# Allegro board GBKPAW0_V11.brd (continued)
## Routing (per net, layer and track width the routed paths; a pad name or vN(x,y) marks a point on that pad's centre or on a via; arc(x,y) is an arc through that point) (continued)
P3V3_IN: length 20.7
  TOP w0.381: R109.2 v1(18.16,5.9)
  TOP w0.508: v1(19.05,5.9) 19.05,8.56 20.57,10.09 23.37,10.09 24,10.72 26.04,10.72 26.67,11.36 L1.2 26.67,14.53
  BOTTOM w0.254: 26.04,17.71 26.04,20.5 R168.2
  BOTTOM w0.381: v1(18.16,5.9) 18.1,5.96 FB129.2 18.03,6.72 R216.2
  vias: v1(28.32,15.3) v1(28.32,14.03) v1(28.32,12.76) v1(28.32,11.49)
P3V3_PG: length 1.4
  TOP w0.254: U7.9 v1(14.5,10.74)
  BOTTOM w0.381: v1(14.5,10.74) 14.51,10.72 R212.1
P3V3EN: length 5.7
  TOP w0.254: C35.2 13.59,9.07 14.2,9.69 U7.11
  TOP w0.381: R110.1 R105.1 C35.2
P5V: length 8.4
  TOP w0.381: R110.2 v1(11.56,5.9) ; R80.1 58.67,15.04 59.05,14.66 v1(59.05,11.36) ; R106.2 v1(13.84,5.9)
  BOTTOM w0.381: v1(51.56,11.99) 51.56,12.67 FB9.1
  vias: v1(13.84,32.69) v1(13.84,31.68) v1(14.73,14.28) v1(14.73,13.39) v1(14.99,32.69) v1(14.99,31.68) v1(15.62,14.28) v1(15.62,13.39) v1(21.08,22.41) v1(21.08,21.52) v1(21.84,23.42) v1(21.84,22.41) v1(21.84,21.14) v1(21.84,19.99) v1(80.52,16.82) v1(81.41,16.82) v1(82.3,14.28) v1(83.06,14.28)
P5V_ADC: length 2.9
  TOP w0.254: U5.2 54.56,15.48 v1(54.74,15.3)
  BOTTOM w0.381: v1(54.74,15.3) 54.61,15.17 C74.2 54.61,14.11 FB9.2
P5VSB: length 7.2
  TOP w0.254: R78.2 17.53,15.93 17.27,16.18 17.27,19.36
  BOTTOM w0.381: R149.1 R151.2 17.78,24.95
  vias: v1(17.53,23.8) v1(17.53,23.04) v1(17.53,22.28)
VBAT: length 22.2
  TOP w0.381: v1(22.35,36.09) 20.61,36.09 R51.2 ; v1(25.65,36.12) 25.65,26.34 C15.2 26.92,25.46 27.3,25.07 27.3,24.57 29.28,22.59 U2.74
  BOTTOM w0.381: v1(25.65,36.12) 25.62,36.09 v1(22.35,36.09)
ADC_IN0: length 2.9
  TOP w0.254: U5.15 52.7,13.77 52.95,13.53 53.2,13.53 ; R103.2 53.72,13.01 53.2,13.53 ; 53.2,13.53 U5.16
ADC_IN1: length 3.2
  TOP w0.254: U5.5 53.7,17.22 53.95,16.97 U5.4 55.54,16.48 R77.2
ADC_IN2: length 3.6
  TOP w0.254: 48.77,16.69 48.98,16.48 U5.9 50.95,16.91 51.27,17.22 U5.8
ADC_IN3: length 2.8
  TOP w0.254: 51.7,13.66 U5.13 ; 51.7,13.66 51.84,13.52 52.07,13.52 52.2,13.65 U5.14 ; 51.7,13.66 51.7,12.77 R102.2
ADCIN0: length 16.4
  TOP w0.254: R100.1 v1(46.55,13.64) ; R100.1 R99.1 ; R100.1 45.85,15.02 R86.2 ; C31.2 R104.1 56.77,12.37 56.39,11.99 v1(54.74,11.99)
  BOTTOM w0.254: v1(46.55,13.64) 46.99,13.64 49.66,10.98 53.72,10.98 v1(54.74,11.99)
ADCIN0+: length 3.5
  TOP w0.254: U5.1 53.95,13.67 54.99,12.63 R104.2
ADCIN1: length 22.5
  TOP w0.254: v1(53.72,11.99) 54.23,11.49 56.63,11.49 57.51,12.36 57.51,13.91 56.88,14.53 C28.2 R88.1 ; v1(45.34,14.28) 44.58,15.04 R85.2 43.43,15.02 R98.1 R97.1
  BOTTOM w0.254: v1(45.34,14.28) 47.24,14.28 50.04,11.49 53.21,11.49 v1(53.72,11.99)
ADCIN1+: length 2
  TOP w0.254: R88.2 55.33,15.98 U5.3
ADCIN2: length 12.4
  TOP w0.254: R96.1 41,13.67 R84.2 41.53,15.04 41.78,15.3 41.78,17.05 42.06,17.33 46.48,17.33 47.12,16.69 47.62,16.69 R87.1 C27.2
ADCIN2+: length 2.5
  TOP w0.254: R87.2 49.07,15.98 U5.10
ADCIN3: length 21.8
  TOP w0.254: v1(49.28,8.31) 42.42,8.31 41.69,9.04 41.69,10.69 R95.1 39.37,12.63 39.12,12.88 39.12,13.46 38.94,13.64 R94.1 38.48,14.94 R83.2 ; v1(47.62,11.99) R101.1 C30.2
  BOTTOM w0.254: v1(49.28,8.31) 49.28,10.34 v1(47.62,11.99)
AI0: length 4.4
  TOP w0.254: R100.2 v1(46.55,12.63)
  BOTTOM w0.254: 48.04,9.58 48.04,10.56 46.55,12.06 v1(46.55,12.63)
AI1: length 4.3
  TOP w0.254: R98.2 v1(44.07,12.63)
  BOTTOM w0.254: v1(44.07,12.63) 45.5,11.19 45.5,9.58
AI2: length 3.9
  TOP w0.254: 42.96,9.58 42.96,10.69 R96.2
AI3: length 3.9
  TOP w0.254: 40.42,9.58 40.42,10.69 R94.2
AI4: length 6.5
  BOTTOM w0.254: 48.04,7.04 46.77,8.31 46.77,10.94 45.85,11.87 R183.2
AI5: length 6.3
  BOTTOM w0.254: R186.2 39.15,12.08 39.15,8.31 40.42,7.04
AI6: length 6.4
  BOTTOM w0.254: R185.2 41.69,11.96 41.69,8.31 42.96,7.04
AI7: length 6.4
  BOTTOM w0.254: R184.2 43.43,11.99 44.23,11.19 44.23,8.31 45.5,7.04
CAN0_RX: length 2.1
  BOTTOM w0.152: R113.1 76.33,64.13 J4.4
CAN0_TX: length 2.4
  BOTTOM w0.152: R112.1 77.47,63.28 J4.3
CAN1_RX: length 2.4
  BOTTOM w0.152: R115.1 74.04,63.47 J4.6
CAN1_TX: length 2
  BOTTOM w0.152: R114.1 75.18,64.32 J4.5
CAN2_RX: length 2.1
  BOTTOM w0.152: R117.1 60.71,64.13 J3.4
CAN2_TX: length 2.4
  BOTTOM w0.152: R116.1 61.85,63.27 J3.3
CAN3_RX: length 2.4
  BOTTOM w0.152: R119.1 58.42,63.47 J3.6
CAN3_TX: length 2
  BOTTOM w0.152: R118.1 59.56,64.32 J3.5
CARD_DET: length 6.2
  BOTTOM w0.152: SDCARD1.9 15.06,45.57 15.49,45.14 17.53,45.14 D36.2 R142.2
CH340_P5V: length 6
  TOP w0.381: v1(23.11,31.55) C13.1 22.95,32.35 U3.1
  BOTTOM w0.381: 22.48,28.88 22.48,30.92 v1(23.11,31.55)
  vias: v1(22.1,27.87) v1(22.1,26.6) v1(23.24,26.6)
CH_RXD: length 7.2
  TOP w0.152: U4.9 21.45,29.38 21.72,29.65 21.72,30.31 22.47,31.07 24.33,31.07 24.77,31.5 24.77,32.57 R56.1
CH_TXD: length 9.6
  TOP w0.152: R54.1 25.15,33.33 25.15,31.35 24.49,30.69 22.63,30.69 22.1,30.15 22.1,29.14 21.34,28.38 U4.8
CHRXD: length 111.4
  TOP w0.152: U3.7 v1(16.38,33)
  BOTTOM w0.152: 62.61,58.48 58.25,58.48 54.88,61.84 54.88,65.15 53.1,66.93 24.58,66.93 20.71,63.06 10.94,63.06 8.76,60.89 8.13,60.89 6.1,58.86 2.41,58.86 0.58,57.03 0.58,37.41 5.05,32.95 7.24,32.95 7.87,33.58 15.8,33.58 v1(16.38,33)
CHTXD: length 110.1
  TOP w0.152: U3.6 16.69,33.65 v1(16.38,33.96)
  BOTTOM w0.152: 62.61,57.33 58.83,57.33 54.48,61.68 54.48,64.98 52.94,66.53 24.74,66.53 20.88,62.67 11.18,62.67 8.89,60.38 8.25,60.38 6.22,58.35 2.62,58.35 1.02,56.74 1.02,37.65 5.38,33.28 6.93,33.28 7.62,33.96 v1(16.38,33.96)
CPU_ADC_IN0: length 24
  TOP w0.254: U2.102 56.49,18.75 57.89,17.35 57.89,15.01 58.44,14.45 v1(58.44,14.04) ; R103.1 v1(52.7,11.99) 52.07,11.36 45.97,11.36 R99.2
  BOTTOM w0.254: v1(52.7,11.99) 53.34,12.63 57.02,12.63 58.44,14.04 v1(58.44,14.04)
CPU_ADC_IN1: length 29.8
  TOP w0.254: U2.100 54.69,20.4 v1(53.21,18.93) ; R97.2 44.07,10.85 56.64,10.85 57.96,12.17 57.96,14.23 57.4,14.79 57.4,16.06 R77.1 56.77,17.55 v1(55.4,18.92)
  BOTTOM w0.254: v1(53.21,18.93) 55.39,18.93 v1(55.4,18.92)
CPU_ADC_IN2: length 6.9
  TOP w0.254: R75.2 R76.1 49.79,17.71 52.89,20.81 U2.98
CPU_ADC_IN3: length 28.6
  TOP w0.254: R102.1 v1(50.55,11.99) ; R95.2 39.75,16.95 41.15,18.34 v1(44.7,18.34) 45.34,18.98 49.4,18.98 51.09,20.66 U2.96
  BOTTOM w0.254: v1(50.55,11.99) 50.55,16.82 49.81,17.56 45.49,17.56 v1(44.7,18.34)
CPU_ADC_IN4: length 16.3
  TOP w0.254: U2.101 55.59,20.34 53.47,18.22 51.66,18.22 50.52,17.07 v1(49.53,17.07)
  BOTTOM w0.254: v1(49.53,17.07) 47.5,15.04 R177.2 C68.2 44.7,13.9 44.96,13.64 R183.1
CPU_ADC_IN5: length 22.5
  TOP w0.254: U2.99 53.79,20.81 52.08,19.11 51.87,19.11 v1(50.73,17.97)
  BOTTOM w0.254: R180.2 C71.2 ; R180.2 38.58,13.67 R186.1 ; R180.2 39.04,15.04 39.32,15.32 39.32,16.9 41.02,18.6 42.67,18.6 43.38,19.31 44.42,19.31 45.76,17.97 v1(50.73,17.97)
CPU_ADC_IN6: length 17.7
  TOP w0.254: v1(41.71,17.84) 45.08,17.84 45.72,18.47 49.65,18.47 51.99,20.81 U2.97
  BOTTOM w0.254: R179.2 41.33,15.04 41.71,15.42 v1(41.71,17.84) ; R179.2 C70.2 ; R179.2 41,13.67 R185.1
CPU_ADC_IN7: length 14.4
  TOP w0.254: U2.95 50.19,20.45 49.22,19.49 44.81,19.49 v1(44.15,18.83)
  BOTTOM w0.254: R184.1 43.41,13.67 R178.2 ; R178.2 C69.2 ; R178.2 43.89,15.04 44.15,15.3 v1(44.15,18.83)
CPU_CAN0_RX: length 18.7
  TOP w0.152: U2.4 61.89,59.15 63.32,60.58 75.9,60.58 v1(76.33,61.02)
  BOTTOM w0.152: R113.2 v1(76.33,61.02)
CPU_CAN0_TX: length 19
  TOP w0.152: v1(77.47,61.02) 76.65,60.2 63.82,60.2 62.79,59.16 U2.3
  BOTTOM w0.152: R112.2 v1(77.47,61.02)
CPU_CAN1_RX: length 22
  TOP w0.152: U2.10 56.49,60.1 57.78,61.4 72.9,61.4 v1(73.28,61.78)
  BOTTOM w0.152: R115.2 v1(73.28,61.78)
CPU_CAN1_TX: length 22.7
  TOP w0.152: v1(75.18,61.02) 58.29,61.02 57.39,60.11 U2.9
  BOTTOM w0.152: R114.2 v1(75.18,61.02)
CPU_CAN2_RX: length 5.6
  TOP w0.152: U2.6 60.09,59.76 v1(60.71,60.38)
  BOTTOM w0.152: v1(60.71,60.38) R117.2
CPU_CAN2_TX: length 5.7
  TOP w0.152: U2.5 60.99,59.52 v1(61.85,60.38)
  BOTTOM w0.152: v1(61.85,60.38) R116.2
CPU_CAN3_RX: length 5.4
  TOP w0.152: v1(58.42,60.38) 58.29,60.25 U2.8
  BOTTOM w0.152: v1(58.42,60.38) R119.2
CPU_CAN3_TX: length 5.5
  TOP w0.152: v1(59.56,60.38) 59.19,60 U2.7
  BOTTOM w0.152: v1(59.56,60.38) R118.2
CPU_DOTESTN: length 2.8
  TOP w0.152: U2.93 v1(48.39,20.23)
  BOTTOM w0.152: v1(48.39,20.23) 48.26,20.36 R160.1 R161.1
CPU_GMAC1_RXCLK: length 38.9
  TOP w0.152: U2.136 v1(66.94,44.19)
  BOTTOM w0.152: v1(66.94,44.19) 66.94,42.46 74.37,35.03 74.37,27.87 73.99,27.49 73.99,18.77 76.83,15.93 76.83,14.79 77.27,14.36 77.9,14.36 78.61,13.64 79.25,13.64 R193.2
CPU_GMAC1_TXCLK_I: length 5.9
  TOP w0.152: U2.135 66.87,43.29 68.45,41.71 68.45,41.29 70.1,39.64 R47.2
CPU_GMAC1_TXCLK_O: length 6.1
  TOP w0.152: U2.134 66.89,42.39 67.94,41.33 67.94,40.66 R49.2
CPU_I2C0_SCL: length 33.6
  TOP w0.152: U2.133 v1(66.94,41.49)
  BOTTOM w0.152: v1(66.94,41.49) 66.94,35.22 69.55,32.62 69.55,29.17 71.37,27.34 71.37,18.09 69.13,15.84 R203.2 R204.2
CPU_I2C0_SDA: length 32.8
  TOP w0.152: U2.132 v1(67.41,40.59)
  BOTTOM w0.152: v1(67.41,40.59) 67.41,35.64 70.05,33 70.05,29.29 71.7,27.64 71.7,17.78 70.27,16.35 R202.2 R201.2
CPU_I2C1_SCL: length 31.5
  TOP w0.152: U2.121 68.04,30.69 v1(69.09,29.65) R64.2 70.36,29.27 70.61,29.01 72.26,29.01 72.64,29.39 72.64,31.81 R58.1
  BOTTOM w0.152: v1(69.09,29.65) 69.09,28.38 70.61,26.85 70.61,18.6 65.66,13.64 R206.2
CPU_I2C1_SDA: length 30.1
  TOP w0.152: R60.1 73.15,31.17 73.15,28.76 72.26,27.87 70.61,27.87 70.36,28.12 R65.2 v1(69.6,28.5) 69.22,28.5 67.93,29.79 U2.120
  BOTTOM w0.152: v1(69.6,28.5) 70.99,27.11 70.99,18.34 66.8,14.15 R205.2
CPU_I2C2_SCL: length 29.6
  TOP w0.152: U2.125 v1(66.94,34.29) 67.02,34.22 R55.2
  BOTTOM w0.152: v1(66.94,34.29) 68.58,32.65 68.58,28.38 70.23,26.73 70.23,18.85 64.55,13.17 R207.2
CPU_I2C2_SDA: length 29.1
  TOP w0.152: R57.2 70.04,33.39 v1(66.94,33.39) U2.124
  BOTTOM w0.152: R208.2 63.73,13.08 63.86,13.08 69.85,19.07 69.85,26.6 68.2,28.25 68.2,32.13 v1(66.94,33.39)
CPU_I2C3_SCL: length 28.8
  TOP w0.152: U2.123 v1(66.94,32.49) 69.8,32.49 R59.2
  BOTTOM w0.152: R209.2 62.85,13.34 63.58,13.34 69.47,19.23 69.47,26.34 67.82,28 67.82,31.62 v1(66.94,32.49)
CPU_I2C3_SDA: length 28.4
  TOP w0.152: U2.122 v1(66.94,31.59) 69.56,31.59 R61.2
  BOTTOM w0.152: v1(66.94,31.59) 67.38,31.16 67.38,27.91 69.09,26.19 69.09,19.49 63.32,13.72 62.09,13.72 R210.2
CPU_I2S_BCLK: length 26
  TOP w0.152: U2.118 66.68,27.99 v1(68.07,26.6)
  BOTTOM w0.152: 58.2,9.58 58.2,11.27 61.37,14.43 61.87,14.43 62.1,14.66 62.1,15.93 62.48,16.31 64.64,16.31 68.33,19.99 68.33,24.44 67.51,25.26 67.51,26.03 v1(68.07,26.6)
CPU_I2S_DI: length 24.9
  TOP w0.152: U2.115 v1(66.94,25.29)
  BOTTOM w0.152: v1(66.94,25.29) 67.94,24.29 67.94,20.25 64.39,16.69 60.83,16.69 60.07,15.93 60.07,13.64 57.28,10.85 56.13,10.85 55.66,10.38 55.66,9.58
CPU_I2S_DO: length 28.3
  TOP w0.152: U2.116 66.32,26.19 66.67,25.84 67.56,25.84 v1(68.07,25.33)
  BOTTOM w0.152: v1(68.07,25.33) 68.71,24.69 68.71,19.68 63.13,14.1 61.54,14.1 59.69,12.25 59.69,10.98 59.18,10.47 59.18,8.95 58.55,8.31 56.93,8.31 55.66,7.04
CPU_I2S_LR: length 26.8
  TOP w0.152: v1(66.94,24.39) U2.114
  BOTTOM w0.152: v1(66.94,24.39) 66.64,24.09 66.64,20.21 63.88,17.45 60.45,17.45 59.26,16.26 59.26,13.8 57.07,11.61 55.75,11.61 54.1,9.96 54.1,8.02 53.12,7.04
CPU_I2S_MCLK: length 26.8
  TOP w0.152: v1(66.93,26.61) 66.79,26.61 66.31,27.09 U2.117
  BOTTOM w0.152: v1(66.93,26.61) 66.33,26.01 66.33,20.41 63.75,17.84 60.2,17.84 58.88,16.51 58.88,13.85 57.02,11.99 55.54,11.99 53.12,9.58
CPU_JTAG_SEL: length 2.8
  TOP w0.152: U2.88 v1(43.89,20.23)
  BOTTOM w0.152: R163.1 R162.1 43.94,20.29 v1(43.89,20.23)
CPU_JTAG_TCK: length 8.6
  TOP w0.152: U2.91 v1(46.59,20.23)
  BOTTOM w0.152: v1(46.59,20.23) 47.46,19.36 53.72,19.36 R170.1
CPU_JTAG_TDI: length 11.3
  TOP w0.152: U2.89 v1(44.79,20.23)
  BOTTOM w0.152: v1(44.79,20.23) 46.3,18.72 51.69,18.72 53.21,17.2 R174.2
CPU_JTAG_TDO: length 13.5
  TOP w0.152: U2.87 v1(42.99,20.23)
  BOTTOM w0.152: v1(42.99,20.23) 43.42,19.8 44.64,19.8 46.03,18.42 51.38,18.42 53.75,16.06 R176.1
CPU_JTAG_TMS: length 8
  TOP w0.152: U2.92 v1(47.49,20.23)
  BOTTOM w0.152: v1(47.49,20.23) 48.06,19.66 52.76,19.66 R167.1
CPU_JTAG_TRST: length 9.9
  TOP w0.152: U2.90 v1(45.69,20.23)
  BOTTOM w0.152: v1(45.69,20.23) 46.87,19.05 51.99,19.05 52.7,18.34 R172.1
CPU_LCD_CLK: length 3
  TOP w0.152: FB1.1 35.79,59.15 U2.33
CPU_LCD_DATA0: length 2.9
  TOP w0.152: U2.34 34.89,59.15 R13.1
CPU_LCD_DATA1: length 37.9
  TOP w0.152: R36.1 v1(11.05,47.17) ; R12.2 v1(33.66,58.48) 33.99,58.14 U2.35
  BOTTOM w0.152: v1(11.05,47.17) 11.05,47.63 10.9,47.78 10.06,47.78 9.91,47.93 9.91,48.24 10.06,48.39 10.9,48.39 11.05,48.54 11.05,48.85 10.9,49 10.44,49 10.29,49.15 10.29,49.46 10.44,49.61 10.9,49.61 11.05,49.76 11.05,50.22 12.19,51.36 12.19,54.79 12.77,55.37 15.05,55.37 16.13,56.44 22.35,56.44 24.18,58.27 33.45,58.27 v1(33.66,58.48)
CPU_LCD_DATA2: length 4.2
  TOP w0.152: U2.36 33.09,58.66 R11.1 R10.1
CPU_LCD_DATA3: length 37.6
  TOP w0.152: v1(24.38,57.84) 27.56,57.84 28.96,59.24 R9.1 32.19,57.28 U2.37 ; R34.1 v1(12.45,48.44)
  BOTTOM w0.152: v1(12.45,48.44) 12.45,46.92 12.32,46.79 11.94,46.79 11.68,47.05 11.68,49 11.84,49.15 12.59,49.15 12.74,49.3 12.74,49.61 12.59,49.76 11.84,49.76 11.68,49.91 11.68,50.22 12.57,51.11 12.57,54.67 12.89,54.98 15.35,54.98 16.43,56.06 22.61,56.06 v1(24.38,57.84)
CPU_LCD_DATA4: length 37.7
  TOP w0.152: R32.1 13.08,49.59 15.11,47.55 17.73,47.55 17.88,47.71 17.88,48.67 18.03,48.82 18.34,48.82 18.49,48.67 18.49,47.71 18.64,47.55 18.95,47.55 19.1,47.71 19.1,48.67 19.25,48.82 19.56,48.82 19.71,48.67 19.71,47.71 19.86,47.55 20.17,47.55 20.32,47.71 20.32,48.67 20.47,48.82 20.78,48.82 20.93,48.67 20.93,47.71 21.08,47.55 21.39,47.55 21.54,47.71 21.54,48.67 21.69,48.82 22,48.82 22.15,48.67 22.15,47.71 22.3,47.55 22.63,47.55 24.92,49.84 v1(28.7,49.84) ; U2.38 28.25,54.99 v1(28.19,55.05) R23.2
  BOTTOM w0.152: v1(28.7,49.84) 28.19,50.35 v1(28.19,55.05)
CPU_LCD_DATA5: length 4.6
  TOP w0.152: U2.39 27.62,54.09 R25.2 R27.1
CPU_LCD_DATA6: length 37.4
  TOP w0.152: U2.40 28.75,53.19 v1(28.7,53.14) ; R30.1 16.94,50.73 17.09,50.58 17.09,49.36 17.25,49.2 17.55,49.2 17.7,49.36 17.7,50.58 17.86,50.73 18.16,50.73 18.31,50.58 18.31,49.48 18.47,49.33 18.77,49.33 18.92,49.48 18.92,50.58 19.08,50.73 19.38,50.73 19.53,50.58 19.53,49.48 19.69,49.33 19.99,49.33 20.14,49.48 20.14,50.58 20.3,50.73 20.6,50.73 20.75,50.58 20.75,49.48 20.9,49.33 21.21,49.33 21.36,49.48 21.36,50.58 21.51,50.73 21.82,50.73 21.97,50.58 21.97,49.48 22.12,49.33 22.43,49.33 22.58,49.48 22.58,50.58 22.73,50.73 23.04,50.73 23.19,50.58 23.19,49.48 23.34,49.33 23.65,49.33 23.8,49.48 23.8,50.58 23.95,50.73 25.15,50.73 25.4,50.98 28.32,50.98 v1(28.7,51.36)
  BOTTOM w0.152: v1(28.7,51.36) v1(28.7,53.14)
CPU_LCD_DATA7: length 39
  TOP w0.152: U2.41 28.61,52.29 27.94,51.62 R29.2 27.43,52 27.28,52.15 25.43,52.15 25.15,51.87 24.71,51.87 24.56,52.02 24.56,53.37 24.41,53.52 24.1,53.52 23.95,53.37 23.95,52.02 23.8,51.87 23.49,51.87 23.34,52.02 23.34,53.37 23.19,53.52 22.88,53.52 22.73,53.37 22.73,52.02 22.58,51.87 22.27,51.87 22.12,52.02 22.12,53.37 21.97,53.52 21.66,53.52 21.51,53.37 21.51,52.02 21.36,51.87 21.05,51.87 20.9,52.02 20.9,53.37 20.75,53.52 20.44,53.52 20.29,53.37 20.29,52.02 20.14,51.87 19.84,51.87 19.68,52.02 19.68,53.37 19.53,53.52 19.23,53.52 19.07,53.37 19.07,52.02 18.92,51.87 18.62,51.87 18.46,52.02 18.46,53.37 18.31,53.52 18.01,53.52 17.85,53.37 17.85,52.02 17.7,51.87 R28.1
CPU_LCD_DATA8: length 36.9
  TOP w0.152: U2.42 v1(29.79,51.39) ; R40.1 10.92,42.73 13.03,42.73 13.18,42.88 13.18,43.34 13.33,43.49 13.64,43.49 13.79,43.34 13.79,42.88 13.94,42.73 14.25,42.73 14.4,42.88 14.4,43.34 14.55,43.49 14.86,43.49 15.01,43.34 15.01,42.88 15.16,42.73 15.47,42.73 15.62,42.88 15.62,43.34 15.77,43.49 16.08,43.49 16.23,43.34 16.23,42.88 16.38,42.73 16.69,42.73 16.84,42.88 16.84,43.34 16.99,43.49 17.3,43.49 17.45,43.34 17.45,42.88 17.6,42.73 17.91,42.73 18.06,42.88 18.06,43.34 18.21,43.49 18.52,43.49 18.67,43.34 18.67,42.88 18.82,42.73 19.13,42.73 19.28,42.88 19.28,43.34 19.43,43.49 19.74,43.49 19.89,43.34 19.89,42.88 20.04,42.73 20.35,42.73 20.5,42.88 20.5,43.34 20.65,43.49 20.95,43.49 21.11,43.34 21.11,42.88 21.26,42.73 21.56,42.73 21.72,42.88 21.72,43.34 21.87,43.49 22.17,43.49 22.33,43.34 22.33,42.88 22.48,42.73 22.78,42.73 22.94,42.88 22.94,43.34 23.09,43.49 23.39,43.49 23.55,43.34 23.55,42.88 23.7,42.73 24.38,42.73 27.05,45.39 v1(27.3,45.39)
  BOTTOM w0.152: v1(27.3,45.39) 27.3,45.9 29.21,47.81 29.21,50.81 v1(29.79,51.39)
CPU_LCD_DATA9: length 35.6
  TOP w0.152: v1(29.79,44.63) 26.92,44.63 24.38,42.09 22.45,42.09 22.29,41.94 22.29,41.61 22.14,41.46 21.84,41.46 21.68,41.61 21.68,41.94 21.53,42.09 21.23,42.09 21.07,41.94 21.07,41.61 20.92,41.46 20.62,41.46 20.46,41.61 20.46,41.94 20.31,42.09 20.01,42.09 19.86,41.94 19.86,41.61 19.7,41.46 19.4,41.46 19.25,41.61 19.25,41.94 19.09,42.09 18.79,42.09 18.64,41.94 18.64,41.61 18.48,41.46 18.18,41.46 18.03,41.61 18.03,41.94 17.87,42.09 17.57,42.09 17.42,41.94 17.42,41.61 17.26,41.46 16.96,41.46 16.81,41.61 16.81,41.94 16.65,42.09 16.35,42.09 16.2,41.94 16.2,41.61 16.05,41.46 15.74,41.46 15.59,41.61 15.59,41.94 15.44,42.09 15.13,42.09 14.98,41.94 14.98,41.61 14.83,41.46 14.52,41.46 14.37,41.61 14.37,41.94 14.22,42.09 13.91,42.09 13.76,41.94 13.76,41.61 13.61,41.46 13.3,41.46 13.15,41.61 13.15,41.94 13,42.09 11.54,42.09 v1(11.05,41.6) ; U2.43 v1(29.79,50.49)
  BOTTOM w0.152: R145.1 10.41,42.09 10.9,41.6 v1(11.05,41.6) ; v1(29.79,44.63) 30.35,45.2 30.35,49.93 v1(29.79,50.49)
CPU_LCD_DATA10: length 3.7
  TOP w0.152: U2.44 29.84,49.59 28.96,50.47 R31.1
CPU_LCD_DATA11: length 3.6
  TOP w0.152: R33.1 29.68,49.33 30.32,48.69 U2.45
CPU_LCD_DATA12: length 6.6
  TOP w0.152: R35.1 28.32,47.3 28.63,47.3 28.78,47.45 28.78,48.67 28.93,48.82 29.24,48.82 29.39,48.67 29.39,47.45 29.54,47.3 29.85,47.3 30.34,47.79 U2.46
CPU_LCD_DATA13: length 3.4
  TOP w0.152: U2.47 27.59,46.89 R37.1
CPU_LCD_DATA14: length 36.6
  TOP w0.152: v1(28.19,45.99) 26.63,45.99 25.78,45.14 25.1,45.14 24.94,44.99 24.94,44.28 24.79,44.12 24.49,44.12 24.33,44.28 24.33,44.99 24.18,45.14 23.88,45.14 23.72,44.99 23.72,44.15 23.57,44 23.27,44 23.11,44.15 23.11,44.99 22.96,45.14 22.66,45.14 22.5,44.99 22.5,44.15 22.35,44 22.05,44 21.9,44.15 21.9,44.99 21.74,45.14 21.44,45.14 21.29,44.99 21.29,44.15 21.13,44 20.83,44 20.68,44.15 20.68,44.99 20.52,45.14 20.22,45.14 20.07,44.99 20.07,44.15 19.91,44 19.61,44 19.46,44.15 19.46,44.99 19.3,45.14 18.42,45.14 18.27,44.99 18.27,44.15 18.11,44 17.81,44 17.66,44.15 17.66,44.99 17.5,45.14 17.2,45.14 17.05,44.99 17.05,44.15 16.89,44 16.59,44 16.44,44.15 16.44,44.99 16.28,45.14 14.62,45.14 14.47,44.99 14.47,44.53 14.31,44.38 14.01,44.38 13.86,44.53 13.86,44.99 13.7,45.14 13.4,45.14 13.25,44.99 13.25,44.53 13.09,44.38 12.79,44.38 12.64,44.53 12.64,44.99 12.48,45.14 10.79,45.14 R39.1 ; U2.48 v1(29.79,45.99)
  BOTTOM w0.152: v1(29.79,45.99) v1(28.19,45.99)
CPU_LCD_DATA15: length 38.4
  TOP w0.152: R38.1 11.05,46.67 11.45,46.67 11.61,46.51 11.61,45.8 11.76,45.65 12.06,45.65 12.21,45.8 12.21,46.51 12.37,46.67 12.67,46.67 12.82,46.51 12.82,45.8 12.98,45.65 13.28,45.65 13.43,45.8 13.43,46.51 13.59,46.67 13.89,46.67 14.04,46.51 14.04,45.8 14.2,45.65 14.5,45.65 14.65,45.8 14.65,46.51 14.81,46.67 15.11,46.67 15.26,46.51 15.26,45.8 15.42,45.65 15.72,45.65 15.87,45.8 15.87,46.51 16.02,46.67 17.5,46.67 17.65,46.51 17.65,45.67 17.81,45.52 18.11,45.52 18.26,45.67 18.26,46.27 18.42,46.42 18.72,46.42 18.87,46.27 18.87,45.67 19.03,45.52 19.33,45.52 19.48,45.67 19.48,46.27 19.63,46.42 19.94,46.42 20.09,46.27 20.09,45.67 20.24,45.52 20.55,45.52 20.7,45.67 20.7,46.27 20.85,46.42 21.16,46.42 21.31,46.27 21.31,45.67 21.46,45.52 21.77,45.52 21.92,45.67 21.92,46.27 22.07,46.42 22.38,46.42 22.53,46.27 22.53,45.67 22.68,45.52 22.99,45.52 23.14,45.67 23.14,46.27 23.29,46.42 23.6,46.42 23.75,46.27 23.75,45.67 23.9,45.52 24.21,45.52 24.36,45.67 24.36,46.27 24.51,46.42 24.82,46.42 24.97,46.27 24.97,45.67 25.12,45.52 25.43,45.52 25.58,45.67 25.58,46.27 25.73,46.42 28.56,46.42 29.89,45.09 U2.49
CPU_LCD_DATA16: length 3.8
  TOP w0.152: R41.1 28.51,44.19 U2.50
CPU_LCD_DATA17: length 3.9
  TOP w0.152: U2.51 28.76,43.29 R43.1
CPU_LCD_DATA18: length 4
  TOP w0.152: U2.52 29,42.39 R45.1
CPU_LCD_DATA19: length 36.2
  TOP w0.152: U2.53 29.75,41.49 v1(29.34,41.08) ; v1(12.32,39.55) 12.32,38.79 11.81,38.28 R50.1
  BOTTOM w0.152: v1(29.34,41.08) 29.59,41.08 29.84,41.33 29.84,42.27 30,42.42 30.58,42.42 30.73,42.57 30.73,42.88 30.58,43.03 30,43.03 29.84,43.18 29.84,43.59 29.69,43.74 29.17,43.74 29.02,43.59 29.02,41.74 28.86,41.58 28.56,41.58 28.41,41.74 28.41,43.59 28.25,43.74 27.95,43.74 27.8,43.59 27.8,41.74 27.65,41.58 27.34,41.58 27.19,41.74 27.19,43.59 27.04,43.74 26.42,43.74 22.73,40.06 12.83,40.06 v1(12.32,39.55)
CPU_LCD_DATA20: length 36.8
  TOP w0.152: v1(28.32,41.08) 28.81,40.59 U2.54 ; R48.1 v1(11.05,39.55)
  BOTTOM w0.152: v1(28.32,41.08) 28.83,40.57 30.99,40.57 31.24,40.82 31.24,41.13 31.09,41.28 30.51,41.28 30.35,41.43 30.35,41.74 30.51,41.89 31.09,41.89 31.24,42.04 31.24,44 31.04,44.2 29.36,44.2 29.2,44.35 29.2,45.37 29.05,45.52 28.75,45.52 28.6,45.37 28.6,44.35 28.44,44.2 27.66,44.2 27.51,44.35 27.51,44.73 27.35,44.89 27.05,44.89 26.9,44.73 26.9,44.35 26.74,44.2 26.24,44.2 22.61,40.57 12.7,40.57 11.68,39.55 v1(11.05,39.55)
CPU_LCD_DATA21: length 3.4
  TOP w0.152: U2.55 27.44,39.69 R46.1
CPU_LCD_DATA22: length 36.9
  TOP w0.152: v1(28.7,37.01) 25.15,37.01 24.77,37.39 24.51,37.39 23.29,38.62 23.07,38.62 22.72,38.26 22.5,38.26 22.28,38.48 22.28,38.69 22.64,39.05 22.64,39.26 21.92,39.98 21.62,39.98 21.46,39.83 21.46,39.07 21.31,38.92 21.01,38.92 20.85,39.07 20.85,39.83 20.7,39.98 20.4,39.98 20.24,39.83 20.24,39.07 20.09,38.92 19.79,38.92 19.63,39.07 19.63,39.83 19.48,39.98 19.18,39.98 19.02,39.83 19.02,39.07 18.87,38.92 18.57,38.92 18.41,39.07 18.41,39.83 18.26,39.98 17.96,39.98 17.81,39.83 17.81,39.07 17.65,38.92 17.35,38.92 17.2,39.07 17.2,39.83 17.04,39.98 16.74,39.98 16.59,39.83 16.59,39.07 16.43,38.92 16.13,38.92 15.98,39.07 15.98,39.83 15.82,39.98 15.52,39.98 15.37,39.83 15.37,39.07 15.21,38.92 14.91,38.92 14.76,39.07 14.76,39.83 14.61,39.98 14.3,39.98 14.15,39.83 14.15,39.07 14,38.92 13.69,38.92 13.54,39.07 13.54,39.83 13.39,39.98 11.13,39.98 R44.1 ; U2.56 v1(29.83,38.79)
  BOTTOM w0.152: v1(29.83,38.79) 28.7,37.66 v1(28.7,37.01)
CPU_LCD_DATA23: length 38.1
  TOP w0.152: U2.57 29.96,37.89 29.52,37.44 29.21,37.44 29.06,37.6 29.06,38.38 28.91,38.54 28.6,38.54 28.45,38.38 28.45,37.6 28.3,37.44 27.99,37.44 27.84,37.6 27.84,38.38 27.69,38.54 27.38,38.54 27.23,38.38 27.23,37.6 27.08,37.44 26.77,37.44 26.62,37.6 26.62,38.38 26.47,38.54 26.16,38.54 26.01,38.38 26.01,37.6 25.86,37.44 25.22,37.44 23.76,38.91 23.76,39.12 24.12,39.48 24.12,39.69 23.9,39.91 23.69,39.91 23.33,39.55 23.11,39.55 22.9,39.77 22.9,39.98 23.25,40.34 23.25,40.56 23.04,40.77 22.82,40.77 22.47,40.41 22.25,40.41 21.59,41.08 21.22,41.08 21.06,40.92 21.06,40.59 20.91,40.44 20.61,40.44 20.46,40.59 20.46,40.92 20.3,41.08 20,41.08 19.85,40.92 19.85,40.59 19.69,40.44 19.39,40.44 19.24,40.59 19.24,40.92 19.08,41.08 18.78,41.08 18.63,40.92 18.63,40.59 18.47,40.44 18.17,40.44 18.02,40.59 18.02,40.92 17.86,41.08 17.56,41.08 17.41,40.92 17.41,40.59 17.25,40.44 16.95,40.44 16.8,40.59 16.8,40.92 16.65,41.08 16.34,41.08 16.19,40.92 16.19,40.59 16.04,40.44 15.73,40.44 15.58,40.59 15.58,40.92 15.43,41.08 15.12,41.08 14.97,40.92 14.97,40.59 14.82,40.44 14.51,40.44 14.36,40.59 14.36,40.92 14.21,41.08 13.9,41.08 13.75,40.92 13.75,40.59 13.6,40.44 13.29,40.44 13.14,40.59 13.14,40.92 12.99,41.08 12.68,41.08 12.53,40.92 12.53,40.59 12.38,40.44 12.07,40.44 11.92,40.59 11.92,40.92 11.77,41.08 10.96,41.08 10.29,41.75 R42.1
CPU_LCD_EN: length 3.4
  TOP w0.152: U2.32 36.69,57.13 37.97,58.42 R14.1
CPU_LCD_HSYNC: length 38.5
  TOP w0.152: R26.1 12.7,53.01 13.78,54.09 13.99,54.09 14.35,53.73 14.56,53.73 14.78,53.95 14.78,54.16 14.42,54.52 14.42,54.74 15.75,56.06 17.53,56.06 19.81,58.35 27.39,58.35 30.56,61.52 38.35,61.52 38.54,61.33 38.54,58.16 37.59,57.2 U2.31
CPU_LCD_VSYNC: length 3.1
  TOP w0.152: R15.1 39.12,57.84 38.49,57.21 U2.30
CPU_SDIO1_CLK: length 39.2
  TOP w0.152: v1(49.29,57.35) 49.29,57.35 U2.18
  BOTTOM w0.152: v1(49.29,57.35) 48.03,58.6 47.69,58.6 47.53,58.45 47.53,57.99 47.38,57.84 47.08,57.84 46.92,57.99 46.92,58.45 46.77,58.6 46.47,58.6 46.31,58.45 46.31,57.99 46.16,57.84 45.86,57.84 45.7,57.99 45.7,58.45 45.55,58.6 45.25,58.6 45.09,58.45 45.09,57.99 44.94,57.84 44.64,57.84 44.48,57.99 44.48,58.45 44.33,58.6 44.03,58.6 43.88,58.45 43.88,58.37 43.72,58.22 43.42,58.22 43.27,58.37 43.27,58.45 43.11,58.6 38.73,58.6 36.96,56.82 25.91,56.82 22.61,53.52 22.61,50.98 21.52,49.89 R136.1
CPU_SDIO1_CMD: length 33.9
  TOP w0.152: U2.17 50.19,57.46 v1(49.29,58.36)
  BOTTOM w0.152: v1(49.29,58.36) 48.67,58.98 38.48,58.98 36.63,57.13 25.58,57.13 21.14,52.69 R135.1
CPU_SDIO1_DATA0: length 40.6
  TOP w0.152: U2.16 51.09,57.46 v1(51.99,58.36)
  BOTTOM w0.152: v1(51.99,58.36) 50.54,56.91 42.07,56.91 40.77,58.22 38.99,58.22 37.26,56.49 26.21,56.49 22.99,53.27 22.99,50.45 21.03,48.5 R138.1
CPU_SDIO1_DATA1: length 39.5
  TOP w0.152: U2.15 v1(51.99,57.35)
  BOTTOM w0.152: R140.1 23.37,49.9 23.37,53.01 26.54,56.19 37.59,56.19 39.24,57.84 40.51,57.84 41.82,56.53 51.17,56.53 v1(51.99,57.35)
CPU_SDIO1_DATA2: length 39.2
  TOP w0.152: v1(53.79,58.36) 52.89,57.46 U2.14
  BOTTOM w0.152: R133.1 22.66,55.48 24.97,57.79 34.98,57.79 36.93,59.75 49.54,59.75 49.69,59.9 49.69,60.1 49.84,60.25 50.14,60.25 50.3,60.1 50.3,59.9 50.45,59.75 50.75,59.75 50.91,59.9 50.91,60.1 51.06,60.25 51.36,60.25 51.52,60.1 51.52,59.9 51.67,59.75 52.4,59.75 v1(53.79,58.36)
CPU_SDIO1_DATA3: length 39.4
  TOP w0.152: U2.13 v1(53.79,57.35)
  BOTTOM w0.152: v1(53.79,57.35) 51.77,59.36 50.91,59.36 50.76,59.21 50.76,58.25 50.61,58.09 50.31,58.09 50.15,58.25 50.15,59.21 50,59.36 37.19,59.36 35.26,57.43 25.25,57.43 21.9,54.08 R134.1
CPU_SPI0_CLK: length 23.9
  TOP w0.152: v1(28.81,27.09) U2.69
  BOTTOM w0.152: v1(28.81,27.09) 29.34,26.57 29.34,21.14 32.13,18.34 32.13,9.07 R215.2
CPU_SPI0_CSN: length 22.8
  TOP w0.152: v1(27.8,27.09) 28.7,26.19 U2.70
  BOTTOM w0.152: R213.1 31.37,10.6 31.37,18.09 28.63,20.83 28.63,26.04 27.8,26.87 v1(27.8,27.09)
CPU_SPI0_MISO: length 26
  TOP w0.152: U2.68 28.7,27.99 v1(27.8,28.89)
  BOTTOM w0.152: R214.1 31.75,9.83 31.75,18.19 28.96,20.99 28.96,26.34 28.32,26.97 28.32,28.37 v1(27.8,28.89)
CPU_SPI0_MOSI: length 27.4
  TOP w0.152: v1(28.81,28.89) U2.67
  BOTTOM w0.152: R217.2 30.86,6.66 31.24,6.66 32.51,7.93 32.51,18.47 29.72,21.26 29.72,27.99 v1(28.81,28.89)
CPU_SPI1_CLK: length 21.6
  TOP w0.152: U2.66 29.71,29.79 v1(28.81,30.69)
  BOTTOM w0.152: R190.2 33.02,14.66 33.02,18.47 30.1,21.39 30.1,29.41 v1(28.81,30.69)
CPU_SPI1_CSN: length 26.7
  TOP w0.152: v1(28.81,32.49) 29.71,31.59 U2.64
  BOTTOM w0.152: R187.2 34.54,16.57 34.54,18.47 31.18,21.84 31.18,32 R219.2 29.34,33.33 28.81,32.81 v1(28.81,32.49)
CPU_SPI1_MISO: length 20.2
  TOP w0.152: U2.65 v1(29.83,30.69)
  BOTTOM w0.152: v1(29.83,30.69) 30.48,30.04 30.48,21.52 33.53,18.47 33.53,15.3 R189.2
CPU_SPI1_MOSI: length 22.5
  TOP w0.152: U2.63 v1(29.83,32.49)
  BOTTOM w0.152: R188.2 34.04,15.93 34.04,18.47 30.86,21.65 30.86,31.46 v1(29.83,32.49)
CPU_SPI2_CLK: length 82.3
  TOP w0.152: v1(24.89,61.02) 20.7,61.02 20.32,61.4 18.41,61.4 16.89,59.87 v1(16.26,59.87) R8.1 ; U2.61 v1(28.45,34.29)
  BOTTOM w0.152: v1(28.45,34.29) 27.74,33.58 18.8,33.58 17.64,34.74 5.45,34.74 2.03,38.16 2.03,56.32 3.05,57.33 8.25,57.33 12.45,61.52 13.84,61.52 15.49,59.87 v1(16.26,59.87) ; R127.2 v1(24.89,61.02)
CPU_SPI2_CSN: length 68.9
  TOP w0.152: R22.1 10.67,54.92 v1(11.05,54.92) 13.08,54.92 15.24,57.08 17.14,57.08 19.43,59.36 26.42,59.36 v1(28.07,61.02) ; U2.59 v1(26.67,36.09)
  BOTTOM w0.152: v1(28.07,61.02) 28.32,61.27 R124.2 R220.2 ; v1(26.67,36.09) 26.2,35.62 19.3,35.62 18.67,36.25 6.86,36.25 5.97,37.14 5.97,41.71 6.6,42.35 6.6,50.09 7.11,50.6 7.75,50.6 9.59,52.44 10.48,52.44 11.05,53.01 v1(11.05,54.92)
CPU_SPI2_MISO: length 71.3
  TOP w0.152: v1(27.18,34.29) 28.08,33.39 U2.62 ; R18.1 v1(11.05,58.73) 11.05,58.98 11.43,59.36 17.02,59.36 18.54,60.89 20.07,60.89 20.57,60.38 25.4,60.38 v1(26.04,61.02)
  BOTTOM w0.152: v1(27.18,34.29) 26.85,33.96 19.05,33.96 17.91,35.11 5.8,35.11 4.44,36.46 4.44,42.35 5.46,43.36 5.46,53.73 10.46,58.73 v1(11.05,58.73) ; R126.2 v1(26.04,61.02)
CPU_SPI2_MOSI: length 77.8
  TOP w0.152: U2.60 27.26,35.19 v1(27.18,35.11) ; R19.1 13.33,58.22 16.64,58.22 v1(17.65,59.24) 18.8,60.38 19.81,60.38 20.32,59.87 26.04,59.87 v1(27.18,61.02)
  BOTTOM w0.152: v1(17.65,59.24) 15.6,59.24 13.69,61.14 12.7,61.14 11.81,60.25 11.81,58.73 11.3,58.22 10.67,58.22 5.84,53.4 5.84,42.98 4.95,42.09 4.95,36.67 6.14,35.49 18.16,35.49 19.3,34.35 26.42,34.35 v1(27.18,35.11) ; R125.2 v1(27.18,61.02)
CPU_TIM1_CH1: length 29
  TOP w0.152: U2.28 v1(40.29,57.35)
  BOTTOM w0.152: R144.1 R142.1 23.75,48.88 23.75,52.63 26.99,55.87 38.82,55.87 v1(40.29,57.35)
CPU_TIM1_CH1N: length 38.8
  TOP w0.152: U2.27 41.19,57.55 40.26,58.48 R16.2 39.88,59.24 39.69,59.43 39.69,61.46 39.12,62.03 30.48,62.03 27.3,58.86 19.56,58.86 17.27,56.57 15.46,56.57 13.05,54.16 R24.2
CPU_TIM1_CH2: length 41.6
  TOP w0.152: v1(43.05,60.25) 43.05,59.62 42.67,59.24 R17.2 43.89,57.51 U2.24 ; R6.2 v1(11.05,61.02)
  BOTTOM w0.152: v1(43.05,60.25) 41.66,60.25 39.52,62.39 31.09,62.39 29.26,60.56 22.66,60.56 21.46,59.36 18.41,59.36 15.88,61.9 11.94,61.9 v1(11.05,61.02)
CPU_TIM1_CH2N: length 26.9
  TOP w0.152: U2.23 44.79,59.41 40.64,63.56 R3.2
CPU_TIM1_CH3: length 29.8
  TOP w0.152: R5.2 17.78,61.52 18.16,61.9 29.59,61.9 30.23,62.54 39.62,62.54 40.77,61.4 40.77,58.73 42.09,57.41 U2.26
CPU_TIM1_CH3N: length 7.8
  TOP w0.152: U2.25 42.99,57.23 41.4,58.81 v1(41.4,61.78)
  BOTTOM w0.152: R120.2 v1(41.4,61.78)
CPU_TIM2_CH1: length 6
  TOP w0.152: v1(44.32,61.02) 45.69,59.65 U2.22
  BOTTOM w0.152: R121.2 v1(44.32,61.02)
CPU_TIM2_CH2: length 5.9
  TOP w0.152: U2.21 46.59,59.89 v1(45.47,61.02)
  BOTTOM w0.152: R122.2 v1(45.47,61.02)
CPU_TIM2_CH3: length 5.8
  TOP w0.152: U2.20 47.49,60.14 v1(46.61,61.02)
  BOTTOM w0.152: R123.2 v1(46.61,61.02)
CPU_UART0_RXD: length 14.6
  TOP w0.152: U2.1 v1(64.59,57.35)
  BOTTOM w0.152: R131.2 74.55,54.67 71.63,54.67 68.95,57.35 v1(64.59,57.35) 64.57,57.33 R130.2
CPU_UART0_TXD: length 13.4
  TOP w0.152: v1(64.59,58.36) 63.69,57.46 U2.2
  BOTTOM w0.152: R132.2 72.64,55.3 71.75,55.3 69.22,57.84 65.11,57.84 v1(64.59,58.36) 64.47,58.48 R128.2
CPU_UART1_RXD: length 34.1
  TOP w0.152: v1(73.02,36.99) U2.128
  BOTTOM w0.152: v1(73.02,36.99) 75.31,34.7 75.31,27.87 74.37,26.93 74.37,19.03 77.29,16.11 77.29,15.47 77.52,15.24 78.16,15.24 78.36,15.04 R192.2
CPU_UART1_TXD: length 34.4
  TOP w0.152: U2.129 v1(69.09,37.89)
  BOTTOM w0.152: v1(69.09,37.89) 70.35,36.63 72.14,36.63 73.99,34.78 73.99,28 73.61,27.61 73.61,18.52 76.45,15.68 76.45,14.15 77.22,13.39 78.36,13.39 R194.2
CPU_UART2_RXD: length 29.3
  TOP w0.152: v1(70.99,36.12) 70.06,35.19 U2.126
  BOTTOM w0.152: R196.2 75.86,15.64 73.23,18.27 73.23,27.82 73.53,28.12 73.53,34.6 72.01,36.12 v1(70.99,36.12)
CPU_UART2_TXD: length 30.8
  TOP w0.152: v1(69.6,36.09) U2.127
  BOTTOM w0.152: R197.2 75.6,13.01 75.6,13.35 75.18,13.77 75.18,15.17 72.85,17.5 72.85,27.94 73.15,28.25 73.15,34.35 71.88,35.62 70.07,35.62 v1(69.6,36.09)
CPU_UART3_RXD: length 29.8
  TOP w0.152: U2.130 v1(68.45,38.79)
  BOTTOM w0.152: v1(68.45,38.79) 68.45,36.38 69.72,35.11 71.86,35.11 72.77,34.19 72.77,28.38 72.47,28.07 72.47,16.11 R199.2
CPU_UART3_TXD: length 30.8
  TOP w0.152: v1(67.94,39.69) U2.131
  BOTTOM w0.152: v1(67.94,39.69) 67.94,36 70.56,33.38 70.56,29.32 72.09,27.79 72.09,13.22 R200.2
CPU_USB0_DM: length 13.5
  TOP w0.14: R68.2 72.24,26.24 CHK1.2 71.27,26.24 71.05,26.46 70.73,26.46 70.36,26.09 70.36,24.19 66.15,19.98 64.3,19.98 64,20.28 64,20.51 63.69,20.82 U2.110
CPU_USB0_DP: length 13.1
  TOP w0.14: U2.111 64.59,20.83 64.27,20.51 64.27,20.39 64.41,20.25 66.04,20.25 70.09,24.3 70.09,26.2 70.62,26.73 71.05,26.73 71.27,26.95 CHK1.1 72.11,26.95 R66.2
CPU_USB0_DRVBUS: length 14.9
  TOP w0.254: R82.1 R90.1 R89.1 60.33,14.28 59.44,15.17 59.44,18.72 59.19,18.97 U2.105
CPU_USB0_ID: length 5.9
  TOP w0.152: J8.1 61.1,17.5 D23.1 60.99,17.61 U2.107
CPU_USB1_DM: length 13.4
  TOP w0.14: R70.2 72.24,22.18 CHK2.2 71.27,22.18 71.05,22.4 70.48,22.4 67.04,18.96 63.39,18.96 62.19,20.16 62.19,20.55 61.89,20.85 U2.108
CPU_USB1_DP: length 13
  TOP w0.14: R69.2 72.11,22.89 CHK2.1 71.27,22.89 71.05,22.67 70.37,22.67 66.93,19.23 63.5,19.23 62.46,20.28 62.46,20.47 62.79,20.81 U2.109
CPU_USB1_OC: length 27.4
  TOP w0.152: v1(61.59,20.14) 61.59,19.49 63.12,17.96 67.94,17.96 69.6,19.61 v1(75.69,19.61) ; U2.106 v1(60.09,20.14)
  BOTTOM w0.152: Q5.3 R181.1 81.33,16.39 78.92,16.39 v1(75.69,19.61) ; v1(60.09,20.14) v1(61.59,20.14)
DCIN_DET: length 9.5
  BOTTOM w0.254: R165.1 10.16,13.64 9.29,12.78 CON4.3
EJTAG_TCK: length 2.3
  BOTTOM w0.152: R170.2 TP6.1 R169.2
EJTAG_TDI: length 2.8
  BOTTOM w0.152: R175.2 TP8.1 R174.1
EJTAG_TDO: length 2.8
  BOTTOM w0.152: R176.2 TP9.1 R182.2
EJTAG_TMS: length 2.3
  BOTTOM w0.152: R166.2 TP5.1 R167.2
EJTAG_TRST: length 3.4
  BOTTOM w0.152: R173.2 R171.2 TP7.1 R172.2
GMAC1_RXCLK: length 2.8
  BOTTOM w0.152: J9.5 78.52,10.13 R193.1
GMAC1_TXCLK_I: length 41.5
  TOP w0.152: R47.1 v1(71.88,39.64)
  BOTTOM w0.152: J9.4 82.33,8.31 82.33,10.25 83.19,11.1 83.19,13.26 82.6,13.85 81.84,13.85 81.15,14.53 81.15,15.55 80.7,16.01 78.66,16.01 75.18,19.49 75.18,19.87 76.33,21.01 76.33,35.2 v1(71.88,39.64)
GMAC1_TXCLK_O: length 37.7
  TOP w0.152: R49.1 v1(71.88,38.5)
  BOTTOM w0.152: J9.3 81.07,9.58 82.75,11.26 82.75,13.19 82.42,13.52 81.63,13.52 80.8,14.35 80.8,15.4 80.57,15.63 78.41,15.63 74.8,19.23 74.8,20.12 75.82,21.14 75.82,34.98 72.3,38.5 v1(71.88,38.5)
GPIO82: length 7
  TOP w0.152: CON5.39 7.22,56.17 7.49,56.44 7.49,59.62 8.89,61.02 R6.1
GPIO83: length 5.5
  TOP w0.152: KEY2.2 13.99,62.58 D4.2 14.16,62.54 C2.1 R4.1 R5.1
GPIO84: length 3.4
  TOP w0.152: R24.1 8.78,53.67 CON5.34
GPIO85: length 4.3
  TOP w0.381: R3.1 R2.2 20.39,63.61 D2.2 21.7,64.83 D1.C
I2C0_SCL: length 2.3
  BOTTOM w0.152: J9.13 68.36,11.36 R204.1
I2C0_SDA: length 6
  BOTTOM w0.152: J9.14 69.63,8.31 69.63,9.96 R201.1
I2C1_SCL: length 2.2
  BOTTOM w0.152: J9.15 65.82,11.58 R206.1
I2C1_SDA: length 5.3
  BOTTOM w0.152: J9.16 67.09,8.31 67.09,11.45 R205.1
I2C2_SCL: length 2.7
  BOTTOM w0.152: J9.17 63.28,10.47 R207.1
I2C2_SDA: length 5.8
  BOTTOM w0.152: J9.18 62.01,8.31 62.01,10.34 R208.1
I2C3_SCL: length 2.8
  BOTTOM w0.152: J9.19 60.74,10.22 R209.1
I2C3_SDA: length 5.7
  BOTTOM w0.152: J9.20 59.69,8.09 59.69,10.31 R210.1
LCD_B0: length 37.8
  TOP w0.152: R13.2 v1(34.8,61.02)
  TOP w0.156: CON5.21 v1(8.38,47.17)
  BOTTOM w0.152: v1(34.8,61.02) 32.44,58.65 23.93,58.65 22.23,56.95 15.88,56.95 14.67,55.75 12.51,55.75 11.81,55.05 11.81,51.74 8.38,48.31 v1(8.38,47.17)
LCD_B1: length 3.4
  TOP w0.156: R36.2 8.77,47.67 CON5.22
LCD_B2: length 37.6
  TOP w0.152: R11.2 v1(32.51,61.02)
  TOP w0.156: CON5.23 v1(7.47,48.17)
  BOTTOM w0.152: v1(32.51,61.02) 32.51,60.76 30.78,59.03 23.67,59.03 22.1,57.46 15.75,57.46 14.99,56.7 12.95,56.7 11.48,55.22 11.48,52.18 10.98,51.68 10.77,51.68 10.48,51.97 10.26,51.97 10.05,51.76 10.05,51.54 10.34,51.25 10.34,51.04 10.12,50.82 9.9,50.82 9.61,51.11 9.4,51.11 9.18,50.89 9.18,50.68 9.47,50.39 9.47,50.17 9.26,49.96 9.04,49.96 8.75,50.25 8.54,50.25 8.32,50.03 8.32,49.82 8.61,49.53 8.61,49.31 v1(7.47,48.17)
LCD_B3: length 3.3
  TOP w0.156: R34.2 9.04,48.67 CON5.24
LCD_B4: length 3.3
  TOP w0.156: CON5.25 8.85,49.17 R32.2
LCD_B5: length 35.5
  TOP w0.152: R27.2 v1(25.65,52.76) ; CON5.26 v1(7.49,49.67)
  BOTTOM w0.152: v1(25.65,52.76) 24.38,52.76 24.13,52.51 24.13,52.18 24.28,52.03 24.61,52.03 24.77,51.88 24.77,51.57 24.61,51.42 24.28,51.42 24.13,51.27 24.13,50.96 24.28,50.81 24.61,50.81 24.77,50.66 24.77,50.35 24.61,50.2 24.28,50.2 24.13,50.05 24.13,48.7 21.21,45.78 21.21,44.07 20.88,43.74 15.37,43.74 14.61,42.98 12.45,42.98 12.19,43.24 12.19,45.9 11.43,46.66 8.25,46.66 6.98,47.93 6.98,49.16 v1(7.49,49.67)
LCD_B6: length 3.4
  TOP w0.156: R30.2 8.71,50.17 CON5.27
LCD_B7: length 3.7
  TOP w0.156: CON5.28 8.07,50.67 R28.2
LCD_CLK: length 38.4
  TOP w0.152: v1(35.94,61.02) FB1.2 36,60.25 C3.1 ; CON5.30 v1(8.13,51.67)
  BOTTOM w0.152: v1(8.13,51.67) 8.64,52.18 8.64,53.12 9.22,53.7 9.43,53.7 9.97,53.17 10.18,53.17 10.4,53.38 10.4,53.6 9.87,54.13 9.87,54.35 10.95,55.43 11.18,55.43 12.83,57.08 14.73,57.08 15.62,57.97 21.97,57.97 23.42,59.41 30.53,59.41 31.94,60.82 31.94,61.05 32.33,61.45 35.51,61.45 v1(35.94,61.02)
LCD_DE: length 37
  TOP w0.152: R14.2 v1(37.97,61.02) ; CON5.33 v1(7.49,53.17)
  BOTTOM w0.152: v1(7.49,53.17) 7.49,53.52 11.05,57.08 11.43,57.08 12.19,57.84 14.22,57.84 15.19,58.81 21.54,58.81 22.91,60.18 29.39,60.18 31.29,62.08 36.91,62.08 v1(37.97,61.02)
LCD_G0: length 3.5
  TOP w0.156: R40.2 8.58,42.67 CON5.12
LCD_G1: length 3.6
  TOP w0.156: CON5.13 v1(7.49,43.17)
  BOTTOM w0.152: v1(7.49,43.17) 8.57,42.09 R145.2
LCD_G2: length 36.5
  TOP w0.152: R31.2 v1(25.65,50.47)
  TOP w0.156: CON5.14 v1(8.38,43.67)
  BOTTOM w0.152: v1(8.38,43.67) 8.38,42.99 8.76,42.6 10.72,42.6 12.24,41.08 22.48,41.08 26.8,45.39 26.8,46.03 27.81,47.05 27.81,52.61 27.66,52.76 26.31,52.76 26.16,52.61 26.16,50.98 v1(25.65,50.47)
LCD_G3: length 36.6
  TOP w0.152: R33.2 v1(25.02,49.33)
  TOP w0.156: CON5.15 v1(7.49,44.17)
  BOTTOM w0.152: v1(25.02,49.33) 25.7,49.33 25.86,49.18 25.86,48.21 26.01,48.06 26.31,48.06 26.47,48.21 26.47,49.18 26.62,49.33 27.05,49.33 27.3,49.08 27.3,47.05 26.42,46.16 26.42,45.7 26.15,45.44 25.94,45.44 25.42,45.96 25.2,45.96 24.99,45.74 24.99,45.53 25.51,45.01 25.51,44.79 22.22,41.51 12.36,41.51 9.72,44.15 9.5,44.15 9.35,44 9.35,43.11 9.22,42.98 9.01,42.98 8.86,43.13 8.86,44.02 8.71,44.17 v1(7.49,44.17)
LCD_G4: length 33.5
  TOP w0.152: R35.2 v1(24.59,48.19)
  TOP w0.156: CON5.16 v1(8.38,44.67)
  BOTTOM w0.152: v1(8.38,44.67) 9.67,44.67 12.37,41.97 20.45,41.97 21.05,42.57 21.26,42.57 21.75,42.08 21.96,42.08 22.18,42.3 22.18,42.51 21.69,43 21.69,43.21 21.91,43.43 22.13,43.43 22.61,42.95 22.82,42.95 23.04,43.16 23.04,43.38 22.56,43.86 22.56,44.07 22.77,44.29 22.99,44.29 23.47,43.81 23.69,43.81 23.9,44.02 23.9,44.24 23.42,44.72 23.42,44.94 23.64,45.15 23.85,45.15 24.33,44.67 24.55,44.67 24.76,44.89 24.76,45.1 24.28,45.58 24.28,45.8 24.59,46.11 24.59,46.82 24.74,46.97 25.5,46.97 25.65,47.12 25.65,47.43 25.5,47.58 24.74,47.58 24.59,47.73 v1(24.59,48.19)
LCD_G5: length 36.7
  TOP w0.152: R37.2 v1(23.88,47.05)
  TOP w0.156: CON5.17 v1(7.49,45.17)
  BOTTOM w0.152: v1(7.49,45.17) 7.95,45.17 8.1,45.32 8.1,46.13 8.25,46.28 8.56,46.28 8.71,46.13 8.71,45.32 8.86,45.17 9.75,45.17 9.97,44.95 10.18,44.95 11.17,45.94 11.39,45.94 11.61,45.73 11.61,45.51 10.61,44.52 10.61,44.3 12.31,42.61 14.87,42.61 15.49,43.24 16.08,43.24 16.23,43.08 16.23,42.68 16.38,42.52 16.69,42.52 16.84,42.68 16.84,43.08 16.99,43.24 17.3,43.24 17.45,43.08 17.45,42.68 17.6,42.52 17.91,42.52 18.06,42.68 18.06,43.08 18.21,43.24 18.52,43.24 18.67,43.08 18.67,42.68 18.82,42.52 19.13,42.52 19.28,42.68 19.28,43.08 19.43,43.24 19.74,43.24 19.89,43.08 19.89,42.68 20.04,42.52 20.35,42.52 20.5,42.68 20.5,43.08 20.65,43.24 20.95,43.24 22.09,44.37 22.09,44.71 21.6,45.19 21.6,45.41 21.82,45.62 22.03,45.62 22.58,45.08 22.8,45.08 22.95,45.23 22.95,45.44 22.4,45.99 22.4,46.21 22.62,46.42 22.83,46.42 23.38,45.88 23.6,45.88 24.13,46.41 24.13,46.79 v1(23.88,47.05)
LCD_G6: length 3.6
  TOP w0.156: R39.2 8.23,45.67 CON5.18
LCD_G7: length 3.3
  TOP w0.156: R38.2 9.01,46.17 CON5.19
LCD_HSYNC: length 3.5
  TOP w0.156: R26.2 8.42,52.17 CON5.31
LCD_R0: length 36.3
  TOP w0.152: R41.2 24.38,41.08 v1(24.38,40.06)
  TOP w0.156: CON5.3 v1(7.47,38.17)
  BOTTOM w0.152: v1(24.38,40.06) 23.88,39.55 13,39.55 12.57,39.12 10.62,39.12 10.46,39.27 10.46,40.21 10.62,40.36 11.91,40.36 12.06,40.52 12.06,40.82 11.91,40.97 10.62,40.97 10.46,41.13 10.46,41.43 10.31,41.58 10.01,41.58 9.86,41.43 9.86,39.27 9.7,39.12 9.4,39.12 9.25,39.27 9.25,41.43 9.09,41.58 8.79,41.58 8.64,41.43 8.64,40.49 8.48,40.34 8.03,40.34 7.87,40.19 7.87,39.88 8.03,39.73 8.48,39.73 8.64,39.58 8.64,39.27 8.48,39.12 8.13,39.12 7.89,38.89 7.89,38.59 v1(7.47,38.17)
LCD_R1: length 36.2
  TOP w0.152: v1(24.38,38.92) 25.02,39.55 25.02,40.57 R43.2
  TOP w0.156: CON5.4 v1(8.38,38.67)
  BOTTOM w0.152: v1(24.38,38.92) 24.13,39.17 23.61,39.17 23.46,39.02 23.46,37.67 23.31,37.52 23,37.52 22.85,37.67 22.85,39.02 22.7,39.17 22.39,39.17 22.24,39.02 22.24,37.67 22.09,37.52 21.78,37.52 21.63,37.67 21.63,39.02 21.48,39.17 21.17,39.17 21.02,39.02 21.02,37.67 20.87,37.52 20.57,37.52 20.41,37.67 20.41,39.02 20.26,39.17 19.96,39.17 19.8,39.02 19.8,37.67 19.65,37.52 19.35,37.52 19.19,37.67 19.19,39.02 19.04,39.17 14.89,39.17 14.73,39.02 14.73,38.18 14.58,38.03 14.28,38.03 14.12,38.18 14.12,39.02 13.97,39.17 13.2,39.17 12.7,38.67 v1(8.38,38.67)
LCD_R2: length 36.2
  TOP w0.152: v1(25.65,40.06) R45.2
  TOP w0.156: CON5.5 v1(7.49,39.17)
  BOTTOM w0.152: v1(25.65,40.06) 26.01,40.06 26.16,39.91 26.16,38.05 26.31,37.9 26.77,37.9 26.92,38.05 26.92,38.35 27.08,38.5 27.53,38.5 27.69,38.65 27.69,38.96 27.53,39.11 27.08,39.11 26.92,39.26 26.92,39.57 27.08,39.72 27.53,39.72 27.69,39.87 27.69,40.18 27.53,40.33 27.08,40.33 26.92,40.48 26.92,40.8 26.77,40.95 25.17,40.95 25.02,40.8 25.02,38.28 23.75,37.01 13.72,37.01 12.54,38.19 8.29,38.19 7.79,37.69 7.27,37.69 6.98,37.97 6.98,38.66 v1(7.49,39.17)
LCD_R3: length 3.9
  TOP w0.152: R50.2 8.89,38.66 8.89,38.92 8.14,39.67 CON5.6
LCD_R4: length 3.4
  TOP w0.152: R48.2 8.66,40.17 7.49,40.17
  TOP w0.156: CON5.7 7.49,40.17
LCD_R5: length 36.6
  TOP w0.152: R46.2 v1(25.65,38.92)
  TOP w0.156: CON5.8 v1(7.49,40.67)
  BOTTOM w0.152: v1(25.65,38.92) 25.65,38.28 25.5,38.13 25.5,37.91 25.79,37.62 25.79,37.41 25.58,37.19 25.36,37.19 25.07,37.48 24.85,37.48 24,36.63 21.92,36.63 21.77,36.48 21.77,36.15 21.62,36 21.31,36 21.16,36.15 21.16,36.48 21.01,36.63 20.7,36.63 20.55,36.48 20.55,36.15 20.4,36 20.09,36 19.94,36.15 19.94,36.48 19.79,36.63 13.46,36.63 12.32,37.77 10.98,37.77 10.83,37.62 10.83,36.91 10.68,36.76 10.37,36.76 10.22,36.91 10.22,37.62 10.07,37.77 9.76,37.77 9.61,37.62 9.61,36.91 9.46,36.76 9.15,36.76 9,36.91 9,37.62 8.85,37.77 8.51,37.77 8,37.27 6.86,37.27 6.48,37.65 6.48,39.42 6.63,39.57 6.93,39.57 7.08,39.72 7.08,40.03 6.93,40.18 6.63,40.18 6.48,40.33 6.48,41.43 6.63,41.58 7.34,41.58 7.49,41.43 v1(7.49,40.67)
LCD_R6: length 3.3
  TOP w0.156: CON5.9 8.93,41.17 R44.2
LCD_R7: length 3.4
  TOP w0.156: R42.2 8.85,41.67 CON5.10
LCD_RESETN: length 58.7
  TOP w0.152: v1(13.59,60.63) 13.21,60.63 R7.1 ; v1(26.29,35.11) 26.54,34.85 D17.A ; R20.1 v1(11.05,57.59)
  BOTTOM w0.152: v1(13.59,60.63) 12.95,60.63 12.19,59.87 12.19,58.48 11.3,57.59 v1(11.05,57.59) 10.79,57.59 6.22,53.01 6.22,42.68 5.46,41.92 5.46,36.93 6.52,35.87 18.36,35.87 19.51,34.73 25.91,34.73 v1(26.29,35.11)
LCD_VSYNC: length 38.6
  TOP w0.152: R15.2 v1(39.12,61.02)
  TOP w0.156: CON5.32 v1(8.13,52.67)
  BOTTOM w0.152: v1(39.12,61.02) 38.61,60.51 37.72,60.51 36.45,61.78 31.5,61.78 29.51,59.8 23.16,59.8 21.72,58.35 15.37,58.35 14.48,57.46 12.68,57.46 11.15,55.94 10.92,55.94 8.13,53.14 v1(8.13,52.67)
MB_PWREN: length 80
  TOP w0.152: v1(67.07,23.49) U2.113
  BOTTOM w0.152: R157.1 26.54,21.65 26.77,21.65 30.61,17.81 30.61,13.01 27.56,9.96 24.51,9.96 23.75,9.2 23.75,6.15 24.26,5.64 53.47,5.64 54.61,6.79 54.61,9.96 55.88,11.23 57.15,11.23 59.69,13.77 59.69,16.18 60.58,17.07 64.14,17.07 67.56,20.5 67.56,23 v1(67.07,23.49)
MRESET#: length 94.7
  TOP w0.152: v1(27.3,32.57) 27.3,26.85 28.87,25.29 U2.71 ; KEY1.2 9.33,63.46 D3.2 C1.1 8.25,61.65 6.48,59.87 v1(6.48,57.84)
  BOTTOM w0.152: R211.1 30.99,11.36 30.99,17.96 27.69,21.26 27.69,26.34 27.3,26.73 v1(27.3,32.57) 26.67,33.2 17.78,33.2 16.59,34.4 5.03,34.4 1.52,37.9 1.52,56.57 2.79,57.84 v1(6.48,57.84)
P0_MDIO0+: length 17.8
  TOP w0.127: U2.138 66.38,45.99 66.67,46.27 66.94,46.27 67.39,45.83 67.39,44.22 69.33,42.27 70.5,42.27 D14.2 71.59,42.24 72.07,42.24 72.35,42.52 72.96,42.52 73.28,42.84 73.28,43.77 73.4,43.9 73.78,43.9 73.91,43.77 73.91,42.84 74.23,42.52 76.13,42.52 76.57,42.96 76.67,43.17 76.84,43.23 CON1.2
P0_MDIO0-: length 17.8
  TOP w0.127: CON1.3 76.32,43.49 76.38,43.32 76.3,43.16 75.99,42.85 74.37,42.85 74.24,42.98 74.24,43.91 73.92,44.23 73.27,44.23 72.95,43.91 72.95,42.98 72.82,42.85 72.21,42.85 71.93,42.57 71.59,42.57 D13.2 70.55,42.6 69.47,42.6 67.72,44.35 67.72,44.92 67.84,45.05 67.94,45.05 68.07,45.18 68.07,45.43 67.94,45.56 67.84,45.56 67.72,45.68 67.72,45.96 67.07,46.61 66.63,46.61 66.35,46.89 U2.139
P0_MDIO1+: length 17
  TOP w0.127: v1(72.26,44.72) 71.94,45.04 71.59,45.04 D12.2 70.5,45.06 69.33,45.06 68.76,45.64 68.76,46.6 67.28,48.07 66.66,48.07 66.38,47.79 U2.140
  BOTTOM w0.127: v1(72.26,44.72) 72.56,45.02 73.33,45.02 73.51,45.19 76.08,45.19 76.71,45.82 76.71,46.66 76.83,46.79 77.43,46.79 77.99,45.95 CON1.4
P0_MDIO1-: length 17
  TOP w0.127: U2.141 66.35,48.69 66.64,48.41 67.42,48.41 69.09,46.74 69.09,45.78 69.47,45.39 70.55,45.39 D11.2 71.59,45.37 71.98,45.37 v1(72.26,45.65)
  BOTTOM w0.127: v1(72.26,45.65) 72.56,45.35 73.2,45.35 73.37,45.52 75.95,45.52 76.38,45.95 76.38,46.8 76.6,47.02 76.6,47.78 CON1.7
P0_MDIO2+: length 17.8
  TOP w0.127: U2.142 66.35,49.59 66.63,49.87 67.52,49.87 67.82,49.57 67.82,49.39 67.76,49.32 67.76,49.14 67.93,48.96 68.11,48.96 68.18,49.03 68.36,49.03 69.54,47.86 70.5,47.86 D10.2 71.59,47.83 71.97,47.83 72.2,47.6 72.8,47.6 72.92,47.48 72.92,45.64 73.24,45.32 73.9,45.32 74.22,45.64 74.22,47.48 74.35,47.6 76.04,47.6 76.32,47.32 76.38,47.21 76.32,47.04 CON1.5
P0_MDIO2-: length 17.8
  TOP w0.127: CON1.6 76.84,47.3 76.67,47.35 76.59,47.52 76.17,47.93 74.21,47.93 73.89,47.61 73.89,45.78 73.76,45.65 73.38,45.65 73.25,45.78 73.25,47.61 72.93,47.93 72.34,47.93 72.11,48.16 71.59,48.16 D9.2 70.55,48.19 69.67,48.19 67.66,50.21 66.64,50.21 66.35,50.49 U2.143
P0_MDIO3+: length 17.8
  TOP w0.127: U2.144 66.37,51.39 66.66,51.68 68.22,51.68 69.25,50.65 70.5,50.65 D8.2 71.59,50.63 71.77,50.63 72.25,50.14 72.81,50.14 73.13,50.46 73.13,52.43 73.25,52.56 73.63,52.56 73.76,52.43 73.76,50.46 74.08,50.14 76.13,50.14 76.57,50.58 76.67,50.79 76.84,50.85 CON1.8
P0_MDIO3-: length 17.8
  TOP w0.127: CON1.9 76.32,51.11 76.38,50.94 76.3,50.78 75.99,50.47 74.22,50.47 74.09,50.6 74.09,52.57 73.77,52.89 73.12,52.89 72.8,52.57 72.8,50.6 72.67,50.47 72.39,50.47 71.91,50.96 71.59,50.96 D7.2 70.55,50.98 69.38,50.98 68.36,52.01 67.71,52.01 67.58,52.13 67.58,52.23 67.46,52.35 67.2,52.35 67.07,52.23 67.07,52.13 66.95,52.01 66.67,52.01 66.38,52.29 U2.145
PHY0_LED0: length 41.1
  TOP w0.152: v1(85.34,45.65) 87.88,48.19 87.88,59.14 86.52,60.51 80.49,60.51 77.69,57.71 70.19,57.71 67.47,54.99 U2.148
  BOTTOM w0.152: R141.2 C46.2 v1(85.34,45.65)
PHY0_LED1: length 5.4
  TOP w0.152: C5.2 70.1,54.88 D5.A 69.28,54.79 68.58,54.09 U2.147
PHY0_LED2: length 5.3
  TOP w0.152: U2.146 68.78,53.19 69.22,52.76 C7.2 70.1,53.69 D6.A
PLTRESETN: length 5.2
  TOP w0.152: U2.72 29.26,24.39 27.01,26.64 D17.C
PWM0: length 2.5
  BOTTOM w0.152: J2.6 43.18,63.09 R120.1
PWM1: length 2.2
  BOTTOM w0.152: R121.1 44.32,63.94 J2.5
PWM2: length 1.9
  BOTTOM w0.152: J2.4 45.47,64.51 R122.1
PWM3: length 2.3
  BOTTOM w0.152: R123.1 46.61,63.66 J2.3
SDIO1_CLK: length 6.3
  BOTTOM w0.152: SDCARD1.5 15.23,49.98 15.88,49.33 17.53,49.33 D33.2 R136.2
SDIO1_CMD: length 6
  BOTTOM w0.152: R135.2 D32.2 17.58,52.18 SDCARD1.3
SDIO1_DATA0: length 6.1
  BOTTOM w0.152: SDCARD1.7 17.38,47.77 D34.2 R138.2
SDIO1_DATA1: length 6.2
  BOTTOM w0.152: SDCARD1.8 15.86,46.67 16.13,46.41 17.41,46.41 D35.2 R140.2
SDIO1_DATA2: length 6.2
  BOTTOM w0.152: R133.2 D30.2 17.41,54.79 16.38,54.79 15.97,54.38 SDCARD1.1
SDIO1_DATA3: length 6.1
  BOTTOM w0.152: R134.2 D31.2 17.29,53.28 SDCARD1.2
SPI0_CLK: length 6
  TOP w0.152: J10.6 25.75,7.63 28.37,7.63 v1(28.57,7.42) D26.2
  BOTTOM w0.152: v1(28.57,7.42) 29.21,7.42 R215.1
SPI0_CSN: length 11.9
  TOP w0.152: D24.2 29.01,9.58 v1(28.57,9.58) 28.19,9.96 24.26,9.96 23.88,9.58 22.35,9.58 21.72,8.95 21.72,7.6 J10.1
  BOTTOM w0.152: R213.2 v1(28.58,9.58)
SPI0_MISO: length 9.8
  TOP w0.152: J10.3 23.75,7.63 23.75,8.95 24.35,9.54 27.72,9.54 v1(28.57,8.69) D25.2
  BOTTOM w0.152: R214.2 29.08,8.69 v1(28.57,8.69)
SPI0_MOSI: length 4.8
  TOP w0.152: D27.2 v1(28.57,6.15)
  BOTTOM w0.152: R217.1 v1(28.57,6.15) 27.81,6.91 27.81,7.56 J10.8
SPI1_CLK: length 6.1
  BOTTOM w0.152: 35.34,7.04 34.04,8.35 R190.1
SPI1_CSN: length 3.2
  BOTTOM w0.152: 37.88,9.58 37.88,12.21 R187.1
SPI1_MISO: length 3.1
  BOTTOM w0.152: R189.1 35.34,12.46 35.34,9.58
SPI1_MOSI: length 6.2
  BOTTOM w0.152: 37.88,7.04 36.61,8.31 36.61,12.34 R188.1
SPI2_CLK: length 2.3
  BOTTOM w0.152: J1.6 24.89,63.56 R127.1
SPI2_CSN: length 4.4
  BOTTOM w0.152: R124.1 29.08,63.56 30.89,63.56 J1.3
SPI2_MISO: length 2.7
  BOTTOM w0.152: J1.5 27.9,64.66 R126.1
SPI2_MOSI: length 3.9
  BOTTOM w0.152: R125.1 27.18,63.3 27.43,63.56 28.45,63.56 29.55,64.66 J1.4
T_CS/CT_RST: length 5.9
  TOP w0.152: CON5.35 8.14,54.17 R22.2 R21.1 R20.2
T_MOSI/CT_SDA: length 103
  TOP w0.152: v1(75.44,38.54) 75.56,38.41 75.56,32.57 R60.2 ; CON5.36 7.62,54.67 8.64,55.68 8.64,57.97 8.89,58.22 11.3,58.22 R19.2 11.81,58.22 12.45,57.59 16.89,57.59 v1(19.18,59.87)
  BOTTOM w0.152: v1(19.18,59.87) 25.06,65.76 52.62,65.76 53.71,64.66 53.71,61.36 58.63,56.44 68.45,56.44 70.36,54.54 70.36,43.62 v1(75.44,38.54)
T_SCL/CT_SCL: length 102.1
  TOP w0.152: v1(75.44,39.68) 74.93,39.17 R58.2 ; R8.2 v1(8.51,59.87) 7.87,59.24 7.87,56.19 7.35,55.67 CON5.38
  BOTTOM w0.152: v1(8.51,59.87) 9.14,59.87 11.56,62.29 21.03,62.29 24.9,66.15 52.78,66.15 54.1,64.83 54.1,61.52 58.8,56.82 68.71,56.82 70.87,54.67 70.87,44.12 75.31,39.68 v1(75.44,39.68)
UART0_RXD: length 3.7
  BOTTOM w0.152: D38.A 78.36,56.95 R218.2 78.17,56.77 D28.2 75.75,56.77 R131.1
UART0_TXD: length 3.8
  BOTTOM w0.152: J5.2 74.42,58.66 D29.2 73.21,56.77 R132.1
UART1_RXD: length 2.7
  BOTTOM w0.152: R191.2 82.07,12.86 D39.A 80.14,13.85 R192.1
UART1_TXD: length 4
  BOTTOM w0.152: J9.7 76.96,9.58 78.99,11.61 R194.1
UART1RXD: length 7.9
  BOTTOM w0.152: J9.8 77.25,8.31 79.12,8.31 79.79,8.98 79.79,10.33 D39.C
